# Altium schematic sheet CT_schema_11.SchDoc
size 147 x 119 mm
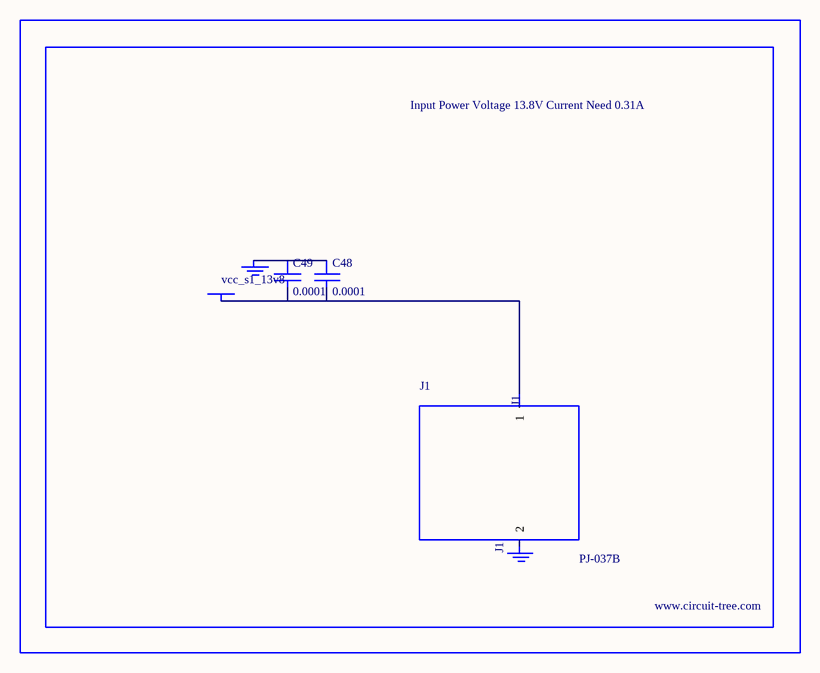
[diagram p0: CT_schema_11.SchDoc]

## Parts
BORDER10  (no value)
C48  0.0001  [EXV-9H]
C49  0.0001  [EXV-9H]
GND_INSTANCE_10_0  (no value)
GND_INSTANCE_10_1  (no value)
J1  PJ-037B  [PJ-037B_PACKAGE]
POWER_INSTANCE_10_0  vcc_s1_13v8

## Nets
NetC48_1: C48.1 C49.1 GND_INSTANCE_10_0.0(GND)
NetC48_2: C48.2 C49.2 J1.1 POWER_INSTANCE_10_0.0(PWR)

Not connected (* = marked no-connect by the designer): GND_INSTANCE_10_1 0(GND); J1 2

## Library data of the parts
BORDER10 = BORDER_PAGE10
C48 C49 = EDK107M035A9HAA
GND_INSTANCE_10_0 GND_INSTANCE_10_1 = GND
POWER_INSTANCE_10_0 = PWR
